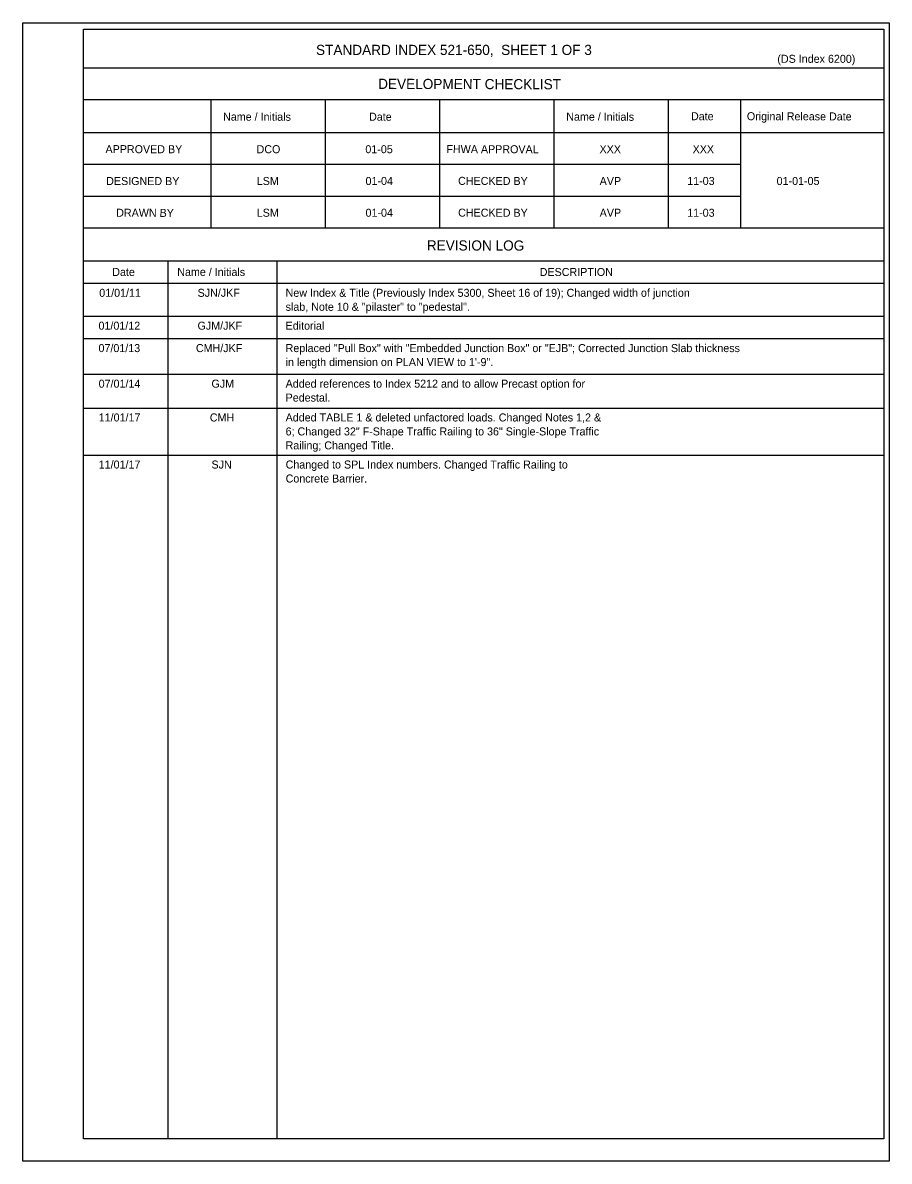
# Model space of a CAD drawing. Extents: x 0 to 54.1, y -0.5 to 22.5.
# Drawn here: x 37.73 to 54.09, y -0.49 to 21.01 of the extents above; entities that cross this region are included whole.
import ezdxf

# ---------------------------------------------------------------- set-up
doc = ezdxf.new("R2010")
doc.units = 0
for name, color, linetype in [('Border', 7, 'Continuous'), ('PlotBorder_dp', 7, 'Continuous'), ('TextStructures', 7, 'Continuous')]:
    doc.layers.add(name, color=color, linetype=linetype)

msp = doc.modelspace()

# ---------------------------------------------------------------- linework, layer by layer
at = {"layer": 'Border'}
for p, q in [((53.991, 20.153), (38.881, 20.153)), ((53.991, 19.553), (38.881, 19.553)), ((41.281, 19.553), (41.281, 17.132)), ((43.441, 19.553), (43.441, 17.132)), ((45.601, 19.553), (45.601, 17.132)), ((47.761, 19.553), (47.761, 17.132)), ((49.921, 19.553), (49.921, 17.132)), ((51.282, 19.553), (51.282, 17.132)), ((53.991, 18.932), (38.881, 18.932)), ((51.282, 18.332), (38.881, 18.332)), ((51.282, 17.732), (38.881, 17.732)), ((53.991, 17.132), (38.881, 17.132)), ((53.991, 16.511), (38.881, 16.511)), ((40.471, 16.511), (40.471, -0.069)), ((42.528, 16.511), (42.528, -0.069)), ((53.991, 16.088), (38.881, 16.088))]:
    msp.add_line(p, q, dxfattribs=at)
msp.add_lwpolyline([(38.881, 20.888), (53.991, 20.888), (53.991, -0.069), (38.881, -0.069)], close=True, dxfattribs=at)
at = {"layer": 'PlotBorder_dp'}
msp.add_line((37.733, -0.49), (37.733, -0.49), dxfattribs=at)
msp.add_lwpolyline([(37.733, 21.01), (54.093, 21.01), (54.093, -0.49), (37.733, -0.49)], close=True, dxfattribs=at)
at = {"layer": 'TextStructures'}
for p, q in [((38.881, 15.467), (53.991, 15.467)), ((38.881, 15.045), (53.991, 15.045)), ((38.881, 14.373), (53.991, 14.373)), ((38.881, 13.735), (53.991, 13.735)), ((38.881, 12.845), (53.991, 12.845))]:
    msp.add_line(p, q, dxfattribs=at)

# ---------------------------------------------------------------- texts
for s, height, p in [('STANDARD INDEX 521-650,  SHEET 1 OF 3', 0.192, (43.27, 20.402)), ('(DS Index 6200)', 0.1512, (51.981, 20.254)), ('DCO', 0.1512, (42.148, 18.547)), ('01-05', 0.1512, (44.202, 18.547)), ('XXX', 0.1512, (48.623, 18.547)), ('XXX', 0.1512, (50.381, 18.547)), ('LSM', 0.1512, (42.151, 17.947)), ('01-04', 0.1512, (44.205, 17.947)), ('AVP', 0.1512, (48.626, 17.947)), ('11-03', 0.1512, (50.279, 17.947)), ('01-01-05', 0.1512, (51.967, 17.947)), ('LSM', 0.1512, (42.151, 17.347)), ('01-04', 0.1512, (44.205, 17.347)), ('AVP', 0.1512, (48.626, 17.347)), ('11-03', 0.1512, (50.279, 17.347)), ('DESCRIPTION', 0.1512, (47.494, 16.228)), ('01/01/11', 0.1512, (39.177, 15.835)), ('SJN/JKF', 0.1512, (41.034, 15.835)), ('New Index & Title (Previously Index 5300, Sheet 16 of 19); Changed width of junction', 0.1512, (42.696, 15.835)), ('slab, Note 10 & "pilaster" to "pedestal".', 0.1512, (42.696, 15.571)), ('01/01/12', 0.1512, (39.163, 15.214)), ('GJM/JKF', 0.1512, (41.033, 15.214)), ('Editorial', 0.1512, (42.696, 15.214)), ('07/01/13', 0.1512, (39.163, 14.791)), ('CMH/JKF', 0.1512, (41.002, 14.791)), ('Replaced "Pull Box" with "Embedded Junction Box" or "EJB"; Corrected Junction Slab thickness', 0.1512, (42.696, 14.791)), ('in length dimension on PLAN VIEW to 1\'-9".', 0.1512, (42.696, 14.527)), ('07/01/14', 0.1512, (39.166, 14.119)), ('GJM', 0.1512, (41.296, 14.119)), ('Added references to Index 5212 and to allow Precast option for ', 0.1512, (42.696, 14.119)), ('Pedestal. ', 0.1512, (42.696, 13.856)), ('11/01/17', 0.1512, (39.167, 13.481)), ('CMH', 0.1512, (41.265, 13.481)), ('Added TABLE 1 & deleted unfactored loads. Changed Notes 1,2 & ', 0.1512, (42.696, 13.481)), ('6; Changed 32" F-Shape Traffic Railing to 36" Single-Slope Traffic ', 0.1512, (42.696, 13.217)), ('Railing; Changed Title.', 0.1512, (42.696, 12.954)), ('11/01/17', 0.1512, (39.167, 12.592)), ('SJN', 0.1512, (41.297, 12.592)), ('Changed to SPL Index numbers. Changed Traffic Railing to ', 0.1512, (42.696, 12.592)), ('Concrete Barrier.', 0.1512, (42.696, 12.328))]:
    msp.add_text(s, height=height, dxfattribs=at).set_placement(p)
for s, height, p in [('DEVELOPMENT CHECKLIST', 0.192, (44.443, 19.761)), ('Name / Initials', 0.1512, (41.515, 19.162)), ('Date', 0.1512, (44.271, 19.161)), ('Name / Initials', 0.1512, (47.995, 19.162)), ('Date', 0.1512, (50.35, 19.17)), ('Original Release Date', 0.1512, (51.405, 19.17)), ('APPROVED BY', 0.1512, (39.295, 18.549)), ('FHWA APPROVAL', 0.1512, (45.732, 18.549)), ('DESIGNED BY', 0.1512, (39.308, 17.947)), ('CHECKED BY', 0.1512, (45.953, 17.949)), ('DRAWN BY', 0.1512, (39.497, 17.347)), ('CHECKED BY', 0.1512, (45.953, 17.349)), ('REVISION LOG', 0.192, (45.362, 16.711)), ('Date', 0.1512, (39.423, 16.229)), ('Name / Initials', 0.1512, (40.65, 16.23))]:
    msp.add_text(s, height=height, rotation=359.8756, dxfattribs=at).set_placement(p)

doc.saveas('drawing.dxf')
